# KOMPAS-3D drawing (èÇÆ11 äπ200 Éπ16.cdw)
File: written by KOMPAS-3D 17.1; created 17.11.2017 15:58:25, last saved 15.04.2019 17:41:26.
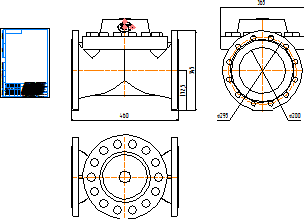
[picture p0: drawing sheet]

Sheet 1: A4, portrait

Title block, sheet 1: name: КАТ11 Ду200 Ру16; material: Внимание! Данный продукт является объектом авторского права ООО «Торговый Дом АДЛ». / Запрещается изменение, копирование, распространение / (в том числе путем копирования на другие сайты и ресурсы в Интернете) / или любое иное использование информации и объектов без предварительного / согласия правообладателя (ООО «Торговый Дом АДЛ»).; mass: 12,4; sheets: 1; organisation: ООО "Торговый дом АДЛ"; sheet format: A4; stored path: \\adlc.lan\data\АДЛ_ПКД\3D-модели\ADL production\Клапаны КАТ ГРАНРЕГ\КАТ11\KOMPAS 2D\КАТ11 Ду200 Ру16.cdw

Views: Вид 1, Проекционный вид 2, Проекционный вид 3
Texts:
  kka
  adl
Dimensions and other numbers on the sheet: 460; 172,5; 345; 295; 365; 200; 1:1; 1; 12,4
